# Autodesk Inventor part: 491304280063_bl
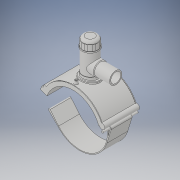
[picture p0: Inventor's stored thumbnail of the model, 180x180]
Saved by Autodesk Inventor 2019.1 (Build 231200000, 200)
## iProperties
Created: 2017-07
Part Number: 491304280063_bl
Material: Generic
Description: PLASSON TAPPING TEE SADDLE 280mm x 63mm
Document SubType Name: Modeling
Designer: KIM
Mass: 1712.7 g
Surface Area: 2671.49 cm^2
Volume: 1712.7 cm^3
Density: 1 g/cm^3
Appearance: Default
Author: KIM
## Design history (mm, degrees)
derived "491304.ipt"
feature "Solid1::491304.ipt" dims "ScaleForDerivedMember" = 10
feature "Solid2::491304.ipt" dims "ScaleForDerivedMember" = 10
feature "Solid4::491304.ipt" dims "ScaleForDerivedMember" = 10
feature "Solid5::491304.ipt" dims "ScaleForDerivedMember" = 10
tag "TaggingFeature1"
body "Solid1"
body "Solid2"
other parameters: "d1" = 101.118 [user parameter], "d2" = 288 [user parameter], "d4" = 176 [user parameter], "d5" = 0 [user parameter], "d6" = 0.1 [user parameter], "d8" = 0 [user parameter], "d40" = 168 [user parameter], "d41" = 97.65 [user parameter], "d43" = 0 [user parameter], "d45" = 0 [user parameter], "d47" = 156.159 [user parameter], "d78" = 175 [user parameter], "d79" = 15 [user parameter], "d80" = 70.4 [user parameter], "d82" = 5 deg [user parameter], "d84" = 4 [user parameter], "d85" = 14 [user parameter], "d86" = 0 [user parameter], "d87" = 3 [user parameter], "d88" = 0 [user parameter], "d97" = 3.52 [user parameter], "d98" = 0 [user parameter], "d102" = 2.8 [user parameter], "d120" = 140 deg [user parameter], "d123" = 606.708 [user parameter], "d126" = 0 [user parameter], "d153" = 176 [user parameter], "d154" = 0 [user parameter], "d159" = -35.7764 [user parameter], "d162" = 105.6 [user parameter], "d163" = 0 [user parameter], "d169" = 4.0905 [user parameter], "d172" = 0 [user parameter], "d173" = 1 [user parameter], "d176" = 20 deg [user parameter], "d177" = 19.6 [user parameter], "d180" = 0 [user parameter], "d184" = 15.68 [user parameter], "d187" = 154 [user parameter], "d188" = 15 [user parameter], "d189" = 19.6 [user parameter], "d190" = 0 [user parameter], "d195" = 90 deg [user parameter], "d197" = 0 [user parameter], "d199" = 0 [user parameter], "d200" = 19.6 [user parameter], "d202" = 0 [user parameter], "d203" = 195 [user parameter], "d206" = 75.6 [user parameter], "d207" = 146.25 [user parameter], "d208" = 152.1 [user parameter], "d209" = 181.35 [user parameter], "d210" = 76.86 [user parameter], "d212" = 72.45 [user parameter], "d213" = 39.15 [user parameter], "d216" = 0 [user parameter], "d217" = 28 [user parameter], "d218" = 14 [user parameter], "d219" = 2.8 [user parameter], "d224" = 0 [user parameter], "d259" = 50.4 [user parameter], "d260" = 63 [user parameter], "d265" = 0 [user parameter], "d267" = 13.00006 [user parameter], "d268" = 2.60001 [user parameter], "d269" = 2.60001 [user parameter], "d271" = 2.60001 [user parameter], "d273" = 0 [user parameter], "d274" = 23.56194 [user parameter], "d275" = 224 [user parameter], "d277" = 112 [user parameter], "d278" = 448 [user parameter], "d280" = 0 [user parameter], "d283" = 0 [user parameter], "d285" = 0 [user parameter], "d290" = 28 [user parameter], "d293" = 154 [user parameter], "d294" = 144.2 [user parameter], "d296" = 42 [user parameter], "d299" = 75 [user parameter], "d300" = 3 [user parameter], "d301" = 5 [user parameter], "d303" = 81.9 [user parameter], "d304" = 69.3 [user parameter], "d305" = 45 deg [user parameter], "d306" = 50.4 [user parameter], "d307" = 175 [user parameter], "d308" = 168 [user parameter], "d310" = 1 [user parameter], "L" = 176 [user parameter], "d_t" = 6 [user parameter], "H2" = 195 [user parameter], "H1" = 75 [user parameter], "d_1" = 63 [user parameter]
